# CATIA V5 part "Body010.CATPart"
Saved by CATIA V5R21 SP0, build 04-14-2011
Part number: Body010
Definition: design
Nomenclature: Body010
Source: Unknown
Bounding box of the stored display mesh (mm): x -0.25 to 0.25, y -1.85 to 1.85, z 0 to 0.1
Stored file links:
  C:\Users\beatr\OneDrive\Documents\UNB\2026_1\Pi1\Componentes eletronicos\Encoder\Body010.CATPart
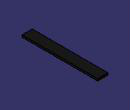
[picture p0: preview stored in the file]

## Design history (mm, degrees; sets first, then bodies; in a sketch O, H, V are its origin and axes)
Body1 "MANIFOLD_SOLID_BREP #5084" (main body)
  Solid1: solid without history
